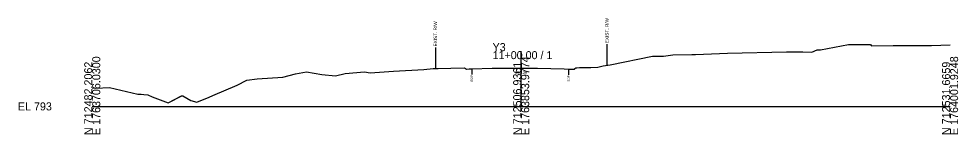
# Model space of a CAD drawing. Extents: x -26 to 2903, y -10 to 5022.
# Drawn here: x -25.7 to 302.8, y 990.3 to 1030.6 of the extents above; entities that cross this region are included whole.
import ezdxf

# ---------------------------------------------------------------- set-up
doc = ezdxf.new("R2010")
doc.units = 0
for name, color, linetype in [('Default', 7, 'Continuous'), ('Exist Cross Section Cell', 7, 'Continuous'), ('Exist XS Center Line Elevation Label', 7, 'Continuous'), ('Exist XS Ground Line', 7, 'Continuous'), ('Old_Level_10', 7, 'Continuous')]:
    doc.layers.add(name, color=color, linetype=linetype)

msp = doc.modelspace()

# ---------------------------------------------------------------- linework, layer by layer
at = {"layer": 'Exist Cross Section Cell'}
for p, q in [((150, 1000), (150, 1019.29)), ((0, 1000), (150, 1000)), ((150, 1000), (300, 1000))]:
    msp.add_line(p, q, dxfattribs=at)
at = {"layer": 'Exist XS Ground Line'}
for points in [[(0, 1006.43), (1.22, 1006.36), (6.03, 1006.62), (15.99, 1004.3), (17.07, 1004.22), (17.98, 1004.2), (19.38, 1004.09), (20.94, 1003.33), (26.5, 1001.25), (31.16, 1003.64), (31.32, 1003.73), (31.7, 1003.72), (34.52, 1002.09), (36.53, 1001.51), (40.87, 1003.21), (42.15, 1003.84), (50.71, 1007.38), (54.06, 1009.13), (57.69, 1009.58), (66.64, 1010.15), (71.12, 1011.31), (74.95, 1012.12), (80.32, 1011.1), (85.09, 1010.62), (88.5, 1011.53), (95.23, 1012.05), (97.18, 1011.74), (105.37, 1012.28), (115.93, 1012.9), (119.24, 1013.18), (120.96, 1013.21), (125.38, 1013.36), (130.22, 1013.44), (130.49, 1013.25), (130.86, 1013.01), (131.81, 1013.07), (132.76, 1013.14), (139.83, 1013.29), (143.98, 1013.37), (150, 1013.36), (153.33, 1013.36), (155.72, 1013.36), (164.99, 1013.1), (166.59, 1013.05), (166.88, 1013.04), (168.46, 1012.96), (168.6, 1013.05), (169.17, 1013.44), (169.46, 1013.45), (170.38, 1013.53), (170.91, 1013.57), (172.59, 1013.6), (174.14, 1013.62), (174.31, 1013.63), (176.84, 1013.69), (178.62, 1014.15), (181.17, 1014.52), (195.93, 1017.51), (198.4, 1017.51), (198.94, 1017.51), (199.73, 1017.57), (202.98, 1018), (209.71, 1018.16), (210.92, 1018.16), (222.19, 1018.54), (242.83, 1019.02), (248.55, 1019.03), (251.7, 1018.94), (253.55, 1019.8), (254.65, 1019.8), (262.02, 1021.12), (264.44, 1021.61), (266.16, 1021.61), (268.46, 1021.61), (272.16, 1021.61), (272.32, 1021.42), (272.57, 1021.11), (280.08, 1021.3), (284.52, 1021.28), (293.54, 1021.21), (300, 1021.45)], [(0, 1006.43), (1.22, 1006.36), (6.03, 1006.62), (15.99, 1004.3), (17.07, 1004.22), (17.98, 1004.2), (19.38, 1004.09), (20.94, 1003.33), (26.5, 1001.25), (31.32, 1003.73), (31.7, 1003.72), (34.52, 1002.09), (36.53, 1001.51), (40.87, 1003.21), (42.15, 1003.84), (50.71, 1007.38), (54.06, 1009.13), (57.69, 1009.58), (66.64, 1010.15), (71.12, 1011.31), (74.95, 1012.12), (80.32, 1011.1), (85.09, 1010.62), (88.5, 1011.53), (95.23, 1012.05), (97.18, 1011.74), (105.37, 1012.28), (115.93, 1012.9), (119.24, 1013.18), (120.96, 1013.21), (125.38, 1013.36), (130.22, 1013.44), (130.86, 1013.01), (131.81, 1013.07), (132.76, 1013.14), (139.83, 1013.29), (143.98, 1013.37), (150, 1013.36), (153.33, 1013.36), (155.72, 1013.36), (164.99, 1013.1), (166.59, 1013.05), (168.46, 1012.96), (169.17, 1013.44), (170.38, 1013.53), (170.91, 1013.57), (172.59, 1013.6), (174.31, 1013.63), (176.84, 1013.69), (178.62, 1014.15), (181.17, 1014.52), (195.93, 1017.51), (198.4, 1017.51), (198.94, 1017.51), (199.73, 1017.57), (202.98, 1018), (209.71, 1018.16), (210.92, 1018.16), (222.19, 1018.54), (242.83, 1019.02), (248.55, 1019.03), (251.7, 1018.94), (253.55, 1019.8), (254.65, 1019.8), (262.02, 1021.12), (264.44, 1021.61), (266.16, 1021.61), (268.46, 1021.61), (272.16, 1021.61), (272.57, 1021.11), (280.08, 1021.3), (284.52, 1021.28), (293.54, 1021.21), (300, 1021.45)]]:
    msp.add_lwpolyline(points, dxfattribs=at)
at = {"layer": 'Old_Level_10'}
for p, q in [((180, 1021.76), (180, 1014.35)), ((120, 1020.6), (120, 1013.2)), ((132.76, 1013.14), (132.76, 1011.09)), ((166.59, 1013.05), (166.59, 1011))]:
    msp.add_line(p, q, dxfattribs=at)

# ---------------------------------------------------------------- texts
at = {"layer": 'Default'}
msp.add_text('-', height=0.0001, dxfattribs=at).set_placement((0, 1000))
at = {"layer": 'Exist Cross Section Cell'}
for s, p in [('Y3', (140, 1019.29)), ('11+00.00 / 1', (140, 1016.49)), ('EL 793', (-26, 998.6))]:
    msp.add_text(s, height=2.8, dxfattribs=at).set_placement(p)
for s, p in [('N 712482.2062', (0, 990)), ('E 1763706.0300', (2.8, 990)), ('N 712506.9361', (150, 990)), ('E 1763853.9774', (152.8, 990)), ('N 712531.6659', (300, 990)), ('E 1764001.9248', (302.8, 990))]:
    msp.add_text(s, height=2.8, rotation=90, dxfattribs=at).set_placement(p)
at = {"layer": 'Exist XS Center Line Elevation Label'}
msp.add_text('806.36', height=1, dxfattribs=at).set_placement((147.86, 1011.36))
at = {"layer": 'Old_Level_10'}
for s, height, p in [('EXIST. R/W', 1.181, (120.59, 1020.9)), ('EXIST. R/W', 1.181, (180.59, 1022.06)), ('EOP', 0.787, (133.16, 1008.69)), ('EOP', 0.787, (166.98, 1008.61))]:
    msp.add_text(s, height=height, rotation=90, dxfattribs=at).set_placement(p)

doc.saveas('drawing.dxf')
